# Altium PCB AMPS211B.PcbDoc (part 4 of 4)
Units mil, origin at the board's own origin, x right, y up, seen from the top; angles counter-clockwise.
Board outline 3600 x 2600 mil, 4 copper layers (Top Layer, GND, Power, Bottom Layer), stack 61.6 mil thick; 202 components, 101 nets, 561 pads, 317 vias.
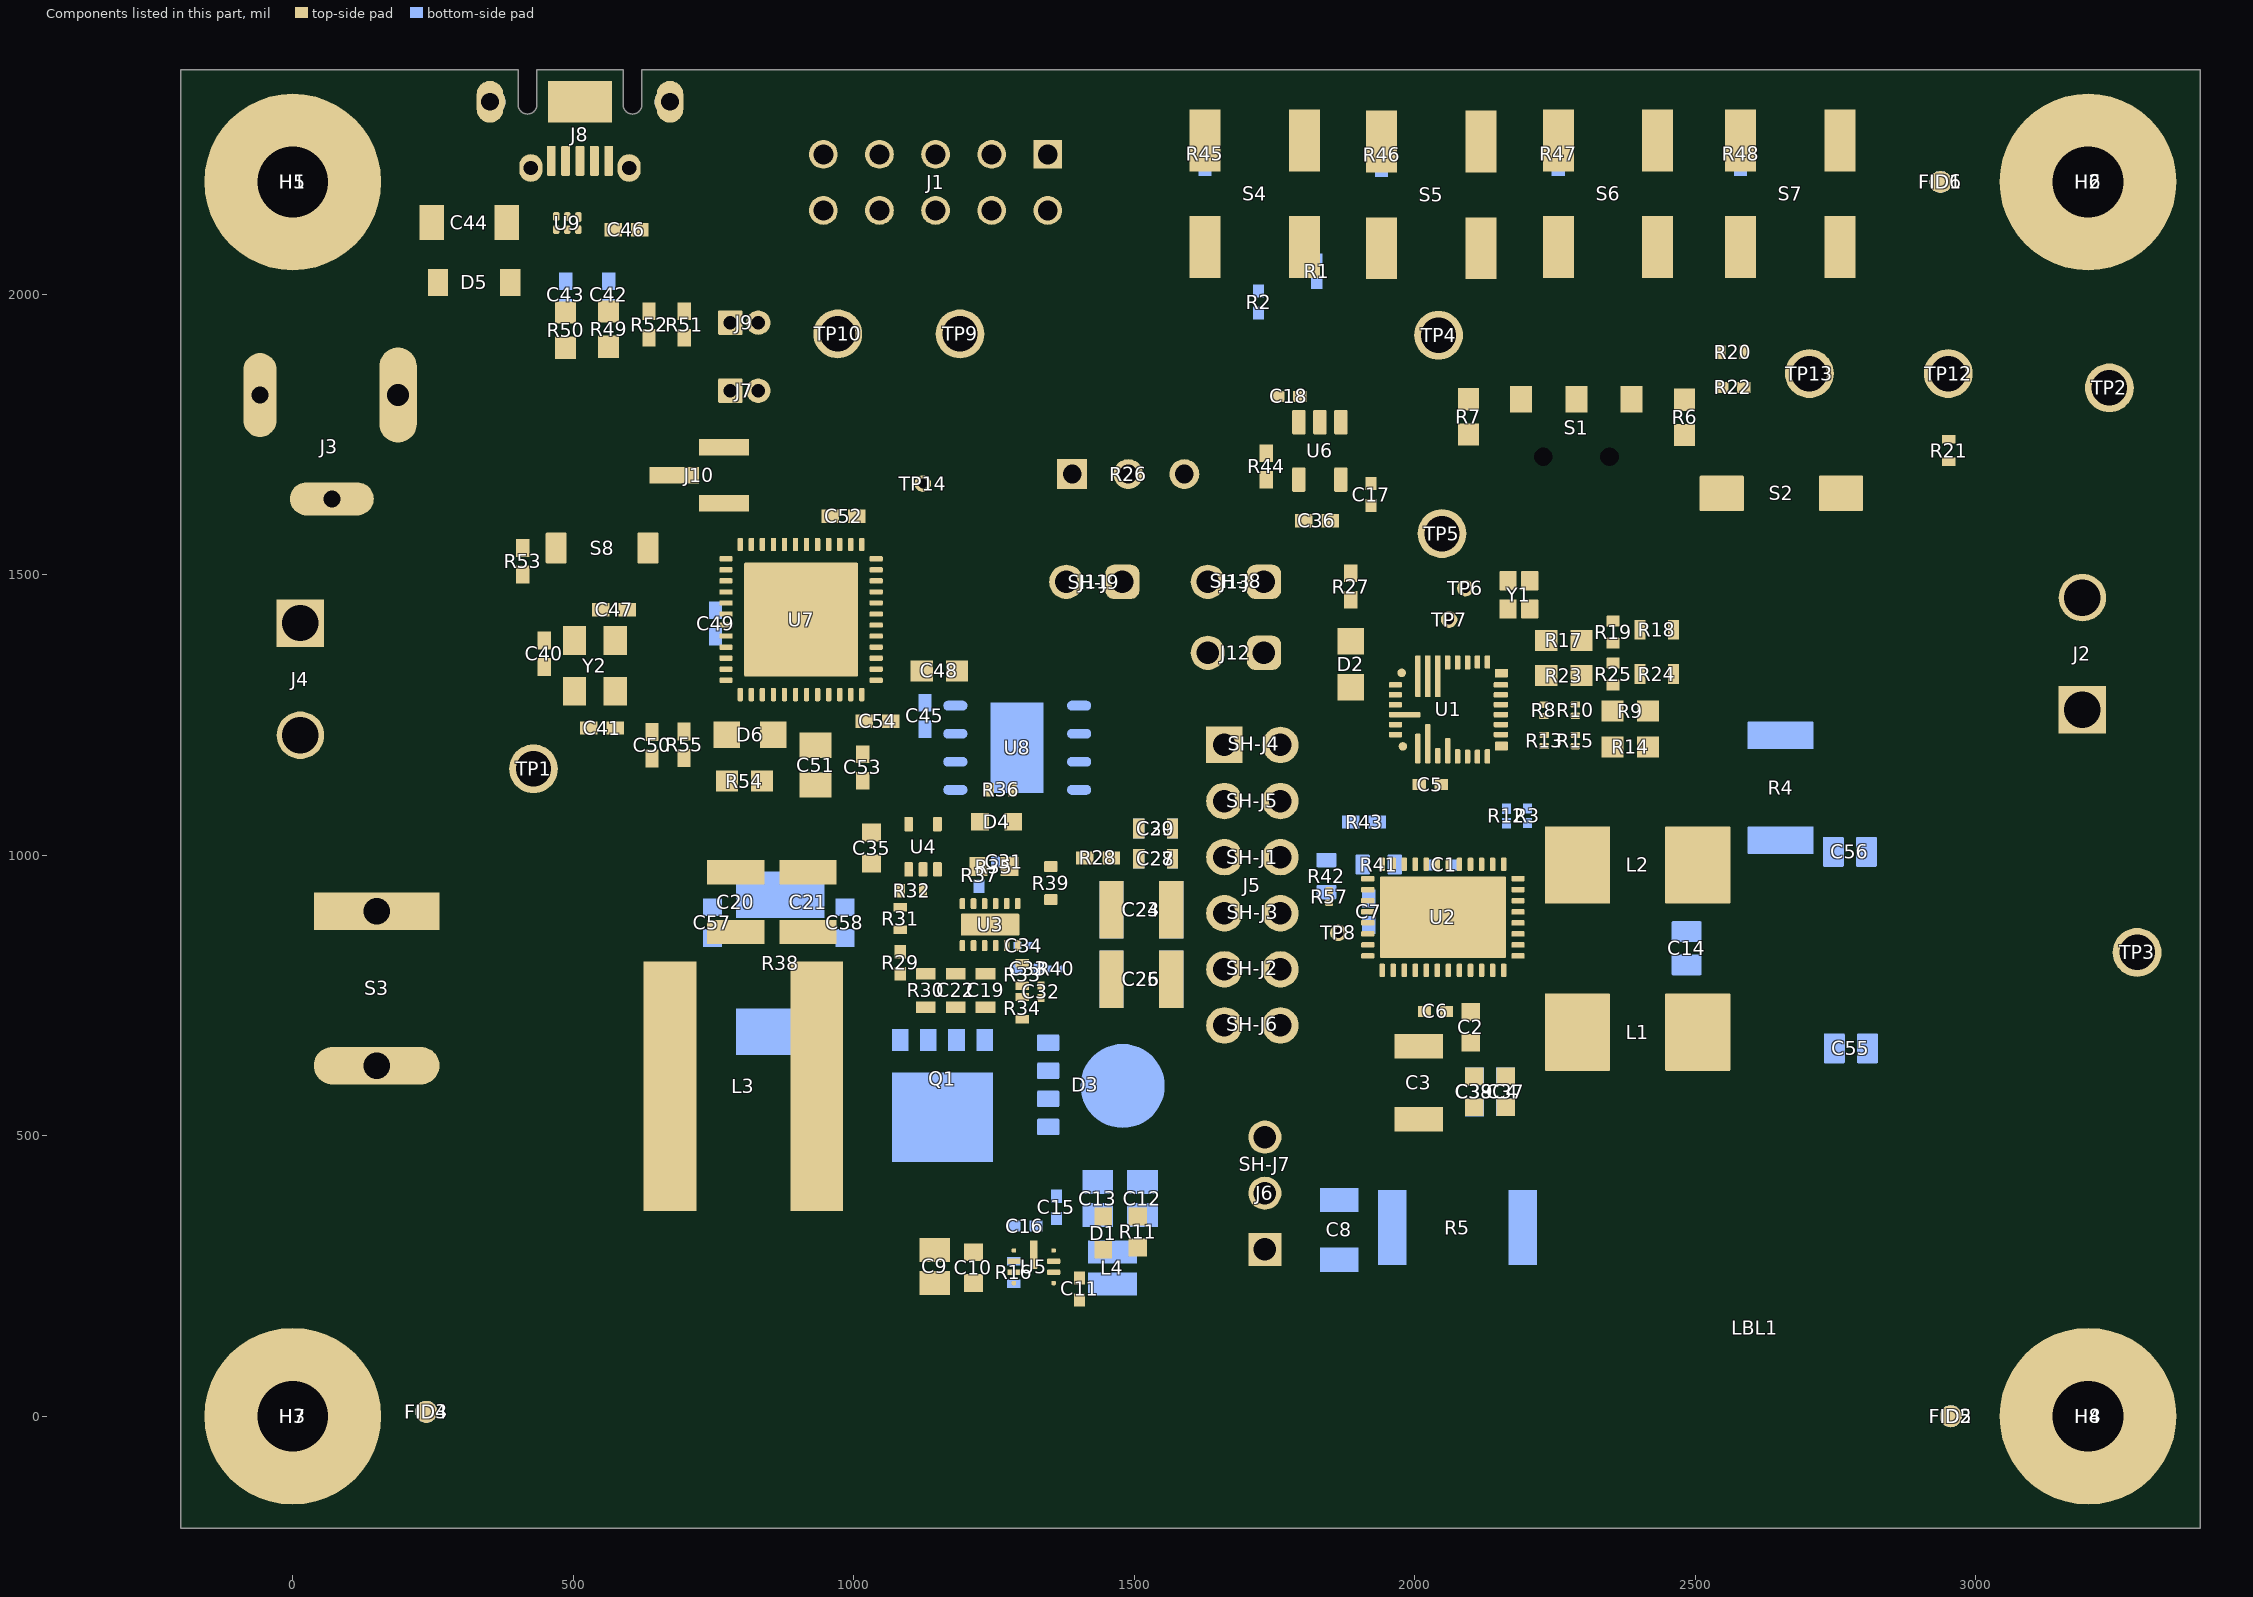
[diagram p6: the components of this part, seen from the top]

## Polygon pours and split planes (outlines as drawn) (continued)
3.3V-DRV on Power "POWER_3.3V-DRV_P401" (solid, remove dead copper, pour order 401): 1709.66,450 1695.84,463.82 1695.84,520.08 1732.77,557 2098,557 2205,664 2205,914 2146,973 2050.62,973 2050.62,1069 2205,1069 2299,975 2299,539 2210,450
VBST on Power "POWER_VBST_P399" (solid, remove dead copper, pour order 399): 1624.65,950.4 1618,957.06 1618,1217.17 1610.49,1224.68 1495.1,1224.68 1481.96,1211.55 1481.96,1089.18 1464.88,1072.1 1219.04,1072.1 1207.82,1060.88 1207.82,992.18 1225.09,974.91 1503.16,974.91 1526.83,951.24 1526.83,659.91 1552.09,634.65 1695.4,634.65 1718.14,657.4 1718.14,922.25 1689.99,950.4
SOURCE on Power "POWER_SOURCE_P400" (solid, remove dead copper, pour order 400): 912.31,805.47 474.72,805.47 425.19,755.95 425.19,562.85 465.43,522.62 519.99,522.62 1320.85,522.62 1334.65,536.42 1334.65,717.52 1246.69,805.47
12VIN_SW on Power "POWER_12VIN_SW_P402" (solid, remove dead copper, pour order 402): 1276.18,469.59 1237.94,507.83 456.64,507.83 276.8,687.68 32.04,687.68 31.65,687.93 -15.06,641.22 -15.06,301.7 214.35,72.3 945.5,72.3 1238.38,72.3 1276.18,110.09
GND on Power "NONET_L-01_P-001" (solid, remove dead copper, pour order 432): 458.32,2100.99 384.46,2027.13 384.46,1291.32 410.88,1269.6 1017.47,1269.6 1032.26,1284.39 1032.26,1484.07 928.16,1588.17 928.16,1808.8 964.57,1845.2 964.57,2037.4 900.98,2100.99
GND on GND "GND_GND_P420" (solid, remove dead copper, pour order 420): 3400,-200 3400,2400 -200,2400 -200,-200
PGND on GND "GND_PGND_P403" (solid, remove dead copper, pour order 403): 1475.4,1794.52 1533.89,1853.02 1878.39,1853.02 1927.18,1804.23 1927.18,1528.38 1724.12,1325.32 1724.12,-98.4 1641.05,-181.47 -188.77,-181.47 -188.79,-181.44 -188.79,1969.1 229.65,1969.1 240.41,1958.3 240.41,1421.35 585.28,1076.47 1435.2,1076.47 1475.4,1116.67

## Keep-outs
Keep-Out Layer:
  lines w5.91: 401.77,2400 401.77,2337.99 ccw(c418.51,2337.74) 435.24,2337.99 435.24,2400 ; 588.78,2400 588.78,2337.99 ccw(c605.51,2337.74) 622.24,2337.99 622.24,2400
  lines w10: -205,-205 3405,-205 3405,2405 -205,2405 -205,-205
  text ".Layer_Name" at 27.84,-1487.26 h60

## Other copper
Top Layer:
  pour cut-out: 2708.66,1441.93 3106.3,1441.93 3106.3,1267.72 2708.66,1267.72
  pour cut-out: 1999.02,1780.51 1978.35,1801.18 1909.45,1801.18 1751.97,1643.7 1702.76,1643.7 1673.23,1673.23 1673.23,1830.71 1692.91,1850.39 1999.02,1850.39
  pour cut-out: 2708.66,1440.94 2708.66,1268.7 2452.76,1268.7 2416.34,1232.28 2416.34,1174.21 2437.01,1153.54 2437.01,1090.55 2429.13,1082.68 2102.36,1082.68 2086.61,1098.43 2086.61,1153.54 2118.11,1185.04 2118.11,1299.21 2259.84,1440.94
  text "1" at 321.27,-4.61 h50
  text ".Layer_Name" at 27.84,-1487.26 h60
Power:
  text "2" at 321.27,-4.61 h50
  text ".Layer_Name" at 27.84,-1487.26 h60
Bottom Layer:
  pour cut-out: 2706.69,1122.05 2706.69,1072.83 2509.84,1072.83 2448.82,1011.81 2440.94,1011.81 2440.94,1106.3 2456.69,1122.05
  pour cut-out: 2708.66,1440.94 2708.66,1122.05 2456.69,1122.05 2437.01,1102.36 2106.3,1102.36 2086.61,1122.05 2086.61,1141.73 2106.3,1161.42 2106.3,1279.53 2267.72,1440.94
  pour cut-out: 2381.89,1417.32 2519.68,1555.12 2519.68,1574.8 2524.89,1580 2574.56,1580 2574.56,1511.57 2480.32,1417.32
  text "4" at 366.72,-10.81 h50
  text ".Layer_Name" at 27.84,-1487.26 h60

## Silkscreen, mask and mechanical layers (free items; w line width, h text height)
Top Overlay:
  circle w6.1: c609.11,1300.84 r3.6
  circle w6.1: c527.76,2137.96 r1.01
  circle w6.1: c247.96,1822.84 r6.29
  circle w6.1: c797.85,1263.45 r2.86
  circle w6.1: c3125.56,856.23 r30
  circle w6.1: c2512.7,1362.53 r30
  circle w6: c2189.48,1861.94 r6
  circle w6: c1571.64,2273.92 r6
  circle w6: c1886.6,2271.95 r6
  circle w6: c2201.56,2273.92 r6
  circle w6: c2526.37,2273.92 r6
  circle w6: c1167.81,842.32 r6
  circle w6: c1062.16,964.12 r6
  circle w6: c1263.88,313.23 r6
  circle w6: c1263.88,313.23 r6
  circle w6: c1062.16,964.12 r6
  circle w6: c1167.81,842.32 r6
  circle w6: c2526.37,2273.92 r6
  circle w6: c2201.56,2273.92 r6
  circle w6: c1886.6,2271.95 r6
  circle w6: c1571.64,2273.92 r6
  circle w6: c2189.48,1861.94 r6
  lines w6: 1141.82,936.56 1148.94,929.44 1148.94,922.54 ; 1307.1,1000.48 1316.5,1009.88 1316.5,1110.55 ; 2106,1503 2166,1563 2307,1563 ; 2316.5,1466.5 2307,1476 2307,1563 ; 2318,1574 2307,1563
  lines w6.1: 706.46,2034.36 734.61,2006.21 ; 887.3,1246.53 898.62,1246.53 ; 1044.1,767.33 1044.1,862.39 1060.13,878.41 ; 1188.56,1107.41 1188.56,1167.99 1212.2,1191.64 ; 1276.94,700.29 1268.64,692 1268.64,560.51 1280.45,548.7 ; 1316.5,1110.55 1324.74,1118.79 ; 1336.95,723.99 1336.95,715.86 1350.72,702.09 ; 1562.71,636.89 1576.62,650.8 1576.62,709.42 ; 1587.89,1090.92 1597.41,1081.39 1597.41,1002.89 1590.36,995.84 ; 2229.07,1176 2239,1176 2263,1152 2347.16,1152 2557,1152 2557,1446 2279.4,1446 2246.62,1413.22 ; 2845.83,406.66 3192.91,406.66 3192.91,908.47 2845.83,908.47 2845.83,406.66
  lines w8: 1515.75,1409.45 1531.5,1409.45 1570.87,1448.82
  text "Custom" at 1607.28,2343.5 h40
  text "Auto" at 1962.6,2343.5 h40
  text "Water" at 2262.8,2343.5 h40
  text "CAL" at 2623.03,2343.5 h40
  text "SCL" at 2120.62,1882.06 h30
  text "SBWTDIO" at 1306.8,1822.3 h30 r90
  text "SBWTCK" at 1096.59,1821.22 h30 r90
  text "SDZ" at 2827.69,1812.43 h30 r90
  text "IRQZ" at 3073.29,1802.63 h30 r90
  text "GND" at 3201,1713 h30
  text "SDA" at 2124,1590 h30
  text "12VIN" at -167.23,1553.24 h30
  text "VarBst" at 1187.1,1553.24 h30
  text "PWMA" at 2421,1523 h30
  text "PWMB" at 2420,1472 h30
  text "RESETZ-MSP" at 1210.72,1383.95 h30
  text "A" at 2528.97,1344.65 h30
  text "RESETZ-ULC" at 1277.65,1309.15 h30
  text "OUTPUT / 0-250Vp / 3.5A / 40-400kHz" at 2608.27,1259.84 h78.74
  text "PGND" at 1485.33,1212.69 h30
  text "GND" at 1825.88,1212.69 h30
  text "Input 9-16V, 8A" at 303.26,1093.73 h98.43 r90
  text "PGND" at 501.04,1070.14 h30
  text "GND" at -170.18,1063.09 h30
  text "A" at 3141.83,838.35 h30
  text "GND" at 3244.19,694.98 h30
  text "VBST" at 1594.58,595.57 h30
  text "PVDD" at 1737.3,595.57 h30
  text "3.3V-DRV" at 1803.24,462.69 h30
  text "3.3V-ULC" at 1803.24,380.02 h30
  text "3.3V-MSP" at 1803.24,287.5 h30
  text "ULC1001-DRV2911EVM" at 2095,287.11 h100
  text "Power Switch" at 555.73,283.86 h120 r90
  text ".Layer_Name" at 27.84,-1487.26 h60
Bottom Overlay:
  lines w6.1: 1175.96,909.31 1206.68,909.31 1215.7,918.34 ; 1234.35,366.03 1234.35,355.99 1247.6,342.74 1264.77,342.74 ; 1235.98,797.23 1272.56,797.23 ; 1354.57,311.17 1354.57,322.32 1361.55,329.3 ; 1364.39,830.99 1364.39,846.98 ; 1453.38,450.01 1457.73,454.36 1586.15,454.36 1590.89,459.1 ; 1553.62,431.4 1637.37,431.4 1650.62,444.65 ; 1574.46,1234.62 1587.31,1221.77 1587.31,1091.13 1612.29,1066.16 1612.29,774.98 1601.4,764.09 ; 1973.94,954.39 1987.96,940.37
  text "'.PRJ_Number'.PCB_Rev" at 2750,0 h100
  text ".Layer_Name" at 27.84,-1487.26 h60
Top Paste:
  region: 382.09,2305.51 346.88,2305.51 338.19,2309.11 331.55,2315.75 327.95,2324.44 327.95,2361.39 331.55,2370.07 338.19,2376.72 346.88,2380.31 382.09,2380.32
  region: 641.93,2305.51 677.14,2305.51 685.82,2309.11 692.47,2315.75 696.06,2324.44 696.06,2361.39 692.47,2370.07 685.82,2376.72 677.14,2380.31 641.93,2380.32
  text ".Layer_Name" at 27.84,-1487.26 h60
Bottom Paste:
  text ".Layer_Name" at 27.84,-1487.26 h60
Top Solder:
  text ".Layer_Name" at 27.84,-1487.26 h60
  text ".Layer_Name" at 27.84,-1487.26 h60
Bottom Solder:
  text ".Layer_Name" at 27.84,-1487.26 h60
Drill Guide:
  text ".Layer_Name" at 27.84,-1487.26 h60
M1 Board Outline:
  the board outline again, w10
  text ".Layer_Name" at 27.84,-1487.26 h60
M2 Board Dimensions:
  rectangle: -549.16,-903.76 -424.16,-778.76
  rectangle: -424.16,-1028.76 -49.16,-903.76
  lines w7: -549.16,-903.76 450.84,-903.76 ; -424.16,-1028.76 -424.16,-778.76 ; -299.16,-1028.76 -299.16,-778.76 ; -49.16,-1028.76 -49.16,-778.76 ; 200.84,-1028.76 200.84,-778.76 ; -549.16,-1028.76 450.84,-1028.76 450.84,-778.76 -549.16,-778.76 -549.16,-1028.76
  lines w10: -200,-200 3400,-200 3400,2400 622.24,2400 622.24,2337.99 cw(c605.51,2337.74) 588.78,2337.99 588.78,2400 435.24,2400 435.24,2337.99 cw(c418.51,2337.74) 401.78,2337.99 401.77,2400 -200,2400 -200,-200
M3 3D STEP Top:
  text ".Layer_Name" at 27.84,-1487.26 h60
M4 3D STEP Bottom:
  text ".Layer_Name" at 27.84,-1487.26 h60
Top M5 Assembly Top/M6 Assembly Bottom:
  lines w6: 7570.15,3565.95 7570.15,4486.58 9154.93,4486.58 ; 7570.15,3638.94 9154.93,3638.94 ; 7570.15,3786.58 9154.93,3786.58 ; 7570.22,3565.58 9154.93,3565.58 ; 7570.22,3713.22 9154.93,3713.22 ; 7570.99,3861.58 9154.61,3861.58 ; 7570.99,3936.58 9154.61,3936.58 ; 7570.99,4011.58 9154.61,4011.58 ; 7570.99,4086.58 9154.61,4086.58 ; 7570.99,4161.58 9154.61,4161.58 ; 7570.99,4236.58 9154.61,4236.58 ; 7570.99,4311.58 9154.61,4311.58 ; 7570.99,4386.58 9154.61,4386.58
  lines w6.1: 7570.15,3786.58 7570.22,3786.51 ; 8052.92,3565.95 8052.92,4486.58 ; 8574.55,3565.95 8574.55,4485.62 ; 9154.93,3565.95 9154.93,4486.58
  lines w10: -841.16,-1558.93 5758.84,-1558.93 ; -841.16,-1355.6 5760.84,-1355.6 ; -841.16,-1152.26 -841.16,-1762.26 3163.84,-1762.26 5760.84,-1762.26 5760.84,-1152.26 -840.66,-1152.26 -840.66,-1762.26 734.84,-1762.26 ; 1623.84,-1762.26 1623.84,-1152.26 ; 2890.84,-1355.6 2890.84,-1152.26 ; 3730.84,-1355.6 3730.84,-1152.26 ; 4352.84,-1768.76 4352.84,-1565.93
  text "Jumper stuff list table" at 7833.34,4548.33 h30
  text "Position" at 8705.13,4422.42 h35
  text "Shunt Ref Des" at 7599.42,4421.7 h35
  text "Header Ref Des" at 8077.59,4419.54 h35
  text "1-2" at 8779.68,4338.41 h35
  text "SH1" at 7739.38,4334.51 h35
  text "J7" at 8272.68,4334.51 h35
  text "J9" at 8272.68,4262.39 h35
  text "1-2" at 8777.7,4262.18 h35
  text "SH2" at 7733.55,4261.08 h35
  text "J5" at 8272.68,4184 h35
  text "5-6" at 8767.98,4183.59 h35
  text "SH-J1" at 7733.55,4181.47 h35
  text "SH-J2" at 7733.55,4112.5 h35
  text "J5" at 8272.68,4112.53 h35
  text "9-10" at 8761.27,4108.38 h35
  text "SH-J3" at 7733.55,4035.13 h35
  text "7-8" at 8770.67,4030.5 h35
  text "J5" at 8272.68,4024.86 h35
  text "SH-J4" at 7733.55,3957.75 h35
  text "1-2" at 8783.86,3955.08 h35
  text "J5" at 8272.68,3953.83 h35
  text "SH-J5" at 7733.55,3882.06 h35
  text "J5" at 8272.68,3880.58 h35
  text "3-4" at 8783.86,3880.08 h35
  text "SH-J6" at 7733.55,3808.05 h35
  text "J5" at 8272.68,3808.44 h35
  text "11-12" at 8783.86,3805.08 h35
  text "1-2" at 8789.86,3735.79 h35
  text "SH-J7" at 7730.9,3734.69 h35
  text "J6" at 8266.16,3729.79 h35
  text "1-2" at 8789.86,3660.99 h35
  text "SH-J8" at 7730.9,3659.89 h35
  text "J13" at 8266.16,3654.99 h35
  text "1-2" at 8789.86,3589.14 h35
  text "SH-J9" at 7730.9,3588.04 h35
  text "J11" at 8266.16,3583.14 h35
  text "COMPONENTS MARKED 'DNP' SHOULD NOT BE POPULATED." at 604.34,-947.26 h60
  text "ASSEMBLY VARIANT:" at 603.84,-1062.76 h60
  text ".VariantName" at 1639.84,-1062.76 h60
  text "PCB VIEWED FROM TOP SIDE" at -777.66,-1284.43 h60
  text "BOARD #:" at 1698.84,-1284.43 h60
  text ".PRJ_Number" at 2244.34,-1284.43 h60
  text "REV:" at 3088.84,-1284.43 h60
  text ".PCB_Rev" at 3380.34,-1284.43 h60
  text "SVN REV:" at 3926.84,-1284.43 h60
  text ".VersionControl_RevNumber" at 4432.84,-1284.43 h60
  text "TID #:" at 1698.84,-1487.76 h60
  text ".TID" at 2244.34,-1487.76 h60
  text "PLOT NAME =" at -777.66,-1693.1 h60
  text ".plot_File_Name" at 27.84,-1693.1 h60
  text "GENERATED    :" at 1700.84,-1693.1 h60
  text ".Print_Date" at 2570.34,-1693.1 h60
  text ".Print_Time" at 3299.34,-1693.1 h60
  text "TEXAS INSTRUMENTS" at 4563.84,-1693.1 h60
Bottom M5 Assembly Top/M6 Assembly Bottom:
  lines w10: -841.66,-1356.1 5760.34,-1356.1 ; -839.66,-1559.43 5760.34,-1559.43 ; 566.34,-1769.26 566.34,-1566.43 ; 1188.34,-1356.1 1188.34,-1152.76 ; 2028.34,-1356.1 2028.34,-1152.76 ; 3295.34,-1762.76 3295.34,-1152.76 ; 4184.34,-1762.76 5759.84,-1762.76 5759.84,-1152.76 -841.66,-1152.76 -841.66,-1762.76 1755.34,-1762.76 5760.34,-1762.76 5760.34,-1152.76
  text "COMPONENTS MARKED 'DNP' SHOULD NOT BE POPULATED." at 5552.84,-946.76 h60
  text ".VariantName" at 4508.84,-1062.76 h60
  text "ASSEMBLY VARIANT:" at 5547.84,-1062.76 h60
  text ".VersionControl_RevNumber" at 486.34,-1284.93 h60
  text "SVN REV:" at 992.34,-1284.93 h60
  text ".PCB_Rev" at 1538.84,-1284.93 h60
  text "REV:" at 1830.34,-1284.93 h60
  text ".PRJ_Number" at 2674.84,-1284.93 h60
  text "BOARD #:" at 3220.34,-1284.93 h60
  text "PCB VIEWED FROM BOTTOM SIDE" at 5696.84,-1284.93 h60
  text ".TID" at 2674.84,-1488.26 h60
  text "TID #:" at 3220.34,-1488.26 h60
  text "TEXAS INSTRUMENTS" at 355.34,-1693.6 h60
  text ".Print_Time" at 1619.84,-1693.6 h60
  text ".Print_Date" at 2348.84,-1693.6 h60
  text "GENERATED    :" at 3218.34,-1693.6 h60
  text ".plot_File_Name" at 4891.34,-1693.6 h60
  text "PLOT NAME =" at 5696.84,-1693.6 h60
M9 Title Sheet:
  drawing of 57 lines, arcs and shapes, not listed
  text "1" at 190.67,7407.74 h70
  text "2" at 2686.34,7407.74 h70
  text "3" at 5175.68,7407.74 h70
  text "4" at 7682.35,7407.74 h70
  text "5" at 10181.34,7407.74 h70
  text "6" at 12686.34,7407.74 h70
  text "A" at -965.66,6264.74 h70
  text "A" at 13834.34,6264.74 h70
  text "B" at -965.66,3884.74 h70
  text "B" at 13834.34,3884.74 h70
  text "C" at -965.66,1509.74 h70
  text "C" at 13834.34,1509.74 h70
  text "PROJECT TITLE:" at 10794.34,-351.26 h45
  text ".PRJ_Title" at 10844.34,-484.59 h70
  text "DESIGNED FOR:" at 10794.34,-652.26 h45
  text ".PRJ_Customer" at 10844.34,-792.26 h70
  text "D" at -965.66,-860.26 h70
  text "D" at 13834.34,-860.26 h70
  text "FILE NAME:" at 10794.34,-952.26 h45
  text ".PCB_File_Name_No_Path" at 10844.34,-1072.26 h70
  text "Texas Instruments (TI) and/or its licensors do not warrant the accuracy or completeness of this specification" at 5824.84,-1234.1 h45
  text "ENGINEER:" at 10794.34,-1242.26 h45
  text "LAYOUT BY:" at 12299.34,-1242.26 h45
  text "or any information contained therein. TI and/or its licensors do not warrant that this design will meet" at 5779.85,-1346.77 h45
  text ".PRJ_Engineer" at 10844.34,-1397.26 h70
  text ".PCB_Layout" at 12349.84,-1397.26 h70
  text "the specifications, will be suitable for your application or fit for any particular purpose, or will operate in" at 5779.85,-1459.43 h45
  text "ALTIUM DESIGNER VERSION:" at 12299.34,-1552.26 h45
  text "an implementation. TI and/or its licensors do not warrant that the design is production worthy. You should" at 5779.85,-1572.1 h45
  text "completely validate and test your design implementation to confirm the system functionality for your application." at 5824.84,-1684.76 h45
  text ".print_Scale" at 10844.34,-1685.59 h70
  text ".Application_BuildNumber" at 12349.84,-1685.59 h70
  text "1" at 190.67,-1892.26 h70
  text "2" at 2686.34,-1892.26 h70
  text "3" at 5175.68,-1892.26 h70
  text "4" at 7682.35,-1892.26 h70
  text "5" at 10181.34,-1892.26 h70
  text "6" at 12299.34,-1897.57 h70
  text "WO:#310005 - 10003-D" at 12495.13,-1897.57 h70
M10 Fab Notes:
  drawing of 199 lines, arcs and shapes, not listed
  text "FAB NOTES:" at -313.49,7134.84 h60
  text "1. BOARD DIMENSION IS : 3600MIL x 2600MIL" at -204.95,6933.26 h60
  text "2. VENDOR MAY ADJUST SOLDERMASK WHEREVER SOLDERMASK PADS ARE THE SAME SIZE (1:1) AS PER THE MANUFACTURING CAPABILITIES AND ALL OTHER SOLDER MASK PADS SHALL NOT BE MODIFIED," at -214.29,6758.42 h60
  text "PROVIDED NO ADJACENT COPPER IS EXPOSED AND NO CONFLICT IS PRODUCED WITH ANY STATED \"VIA TENTING/COVERING\" REQUIREMENTS." at -42.45,6600.66 h60
  text "3. TRACES WITH 6.2MIL TO BE 50 OHMS +/-10% SINGLE ENDED ON EXTERNAL LAYER L1 AND L4(TOP LAYER AND BOTTOM LAYER)." at -194.65,6434.35 h60
  text "4. ALL VIAS ARE TENTED ON TOP SIDES UNLESS OTHERWISE SOLDER MASK IS OPENED IN GERBER." at -201.54,6237.4 h60
  text "DESIGN INFORMATION" at 11832.85,5727.41 h60
  text "MIN. TRACK WIDTH:" at 11188.29,5595.28 h60
  text "6" at 12284.54,5595.29 h60
  text "MIL" at 12439.29,5595.28 h60
  text "5.9" at 12220.59,5481.75 h60
  text "MIN. CLEARANCE:" at 11188.29,5471.16 h60
  text "MIL" at 12439.29,5471.16 h60
  text "19.685" at 12076.02,5348.81 h60
  text "MIN. VIA PAD SIZE:" at 11188.29,5347.03 h60
  text "MIL" at 12439.29,5347.03 h60
  text "0.05mm (2MIL)" at 11883.3,5217.13 h60
  text "MINIMUM ANNULAR RING" at 10859.06,5208.91 h60
  text "EXTERNAL" at 12591.3,5208.91 h60
  text "PER" at 11059.06,5098.78 h60
  text "IPC-D-275 CLASS 2 LEVEL C" at 11279.06,5098.78 h60
  text "MIL, HOLES" at 12767.29,4998.3 h60
  text "+/-" at 12374.84,4989.72 h60
  text "+/-" at 13228.84,4989.72 h60
  text "REGISTRATION TOLERANCES:" at 10859.06,4988.65 h60
  text "METAL" at 12058.84,4988.65 h60
  text "5" at 12635.04,4988.66 h60
  text "3" at 13468.04,4988.66 h60
  text "MIL" at 13584.29,4988.65 h60
  text "HOLE SIZE TOLERANCE (UNLESS OTHERWISE SPECIFIED):" at 10859.06,4890.34 h60
  text "+/-" at 13228.84,4887.47 h60
  text "3" at 13468.04,4886.41 h60
  text "MIL" at 13584.29,4886.4 h60
  text "MATERIAL:" at 10784.3,4748.75 h60
  text "FR-4 High Tg" at 11770.74,4620.23 h60
  text "X" at 11632.22,4617.12 h60
  text "FR-4" at 11205.3,4607.72 h60
  text "OTHER" at 12693.3,4607.72 h60
  text "62 MIL (1.6mm) +/-10%" at 11525.4,4464.69 h60
  text "X" at 11405.3,4462.24 h60
  text "THICKNESS:" at 10859.06,4456.47 h60
  text "OTHER" at 12810.3,4456.47 h60
  text "TOLERANCE:" at 10859.06,4318.16 h60
  text "X" at 11707.3,4318.16 h60
  text "ANSI IPC-6012 TYPE 3 CLASS 2" at 11885.31,4318.16 h60
  text "OTHER +/-" at 11885.3,4173.97 h60
  text "BOW & TWIST:" at 10859.06,4028.78 h60
  text "X" at 11707.3,4028.78 h60
  text "ANSI IPC-6012 TYPE 3 CLASS 2" at 11885.31,4028.78 h60
  text "OTHER +/-" at 11885.3,3882.08 h60
  text "DRILLING:" at 10784.3,3751.46 h60
  text "NC_DRILL FILES" at 12545.29,3646.28 h60
  text "REFERENCE:" at 10859.06,3642.34 h60
  text "X" at 11516.3,3642.24 h60
  text "AS SHOWN" at 11694.29,3642.34 h60
  text "X" at 12417.3,3642.34 h60
  text "OTHER" at 12843.3,3500.09 h60
  text "PTH COPPER THICKNESS:" at 10858.74,3496.56 h60
  text "X" at 11997.98,3496.56 h60
  text "20-30 um" at 12125.97,3496.56 h60
  text "BOARD FINISH:" at 10784.3,3348.96 h60
  text "SILKSCREEN:" at 10939.52,3238.83 h60
  text "X" at 11897.3,3238.83 h60
  text "TOP" at 12014.29,3238.83 h60
  text "X" at 12407.3,3238.83 h60
  text "BOTTOM" at 12525.29,3238.83 h60
  text "SILKSCREEN COLOR:" at 10939.52,3083.65 h60
  text "X" at 11896.3,3083.65 h60
  text "WHITE" at 12014.29,3083.65 h60
  text "OTHER" at 12525.29,3083.65 h60
  text "X" at 12618.25,2941.38 h60
  text "GREEN" at 12145.29,2940.2 h60
  text "OTHER" at 12763.3,2940.2 h60
  text "SOLDER RESIST COLOR:" at 10939.52,2933.33 h60
  text "BLUE" at 13123.7,2928.93 h60
  text "MATTE" at 12145.29,2785.95 h60
  text "X" at 12620.7,2786.51 h60
  text "SEMI-GLOSS" at 12762.84,2785.31 h60
  text "IMMERSION GOLD (ENIG)" at 11845.29,2613.17 h60
  text "ENEPIG" at 13182.84,2605.95 h60
  text "SURFACE FINISH:" at 10784.3,2604.95 h60
  text "X" at 11667.3,2604.95 h60
  text "IMM. TIN/SILVER OR EQUIV" at 11113.84,2467.64 h60
  text "OTHER" at 12545.3,2463.7 h60
  text "ARRAY/PANEL:" at 10784.3,2308.32 h60
  text "CUT AND TRIM PER M1 BOARD OUTLINE" at 11845.3,2300.1 h60
  text "N.C. ROUTE" at 11845.29,2164.13 h60
  text "V. SCORE" at 12711.3,2164.13 h60
  text "CERTIFICATION:" at 10784.3,2035.01 h60
  text "MATERIALS AND WORKMANSHIP FOR ALL PCBS" at 11509.3,2035.01 h60
  text "TO MEET OR EXCEED THE REQUIREMENTS OF:" at 11509.3,1940.94 h60
  text "X" at 11146.8,1812.32 h60
  text "ANSI IPC-A-600F CLASS ->" at 11274.8,1812.32 h60
  text "X" at 12922.8,1812.32 h60
  text "2" at 13032.8,1812.32 h60
  text "1" at 12717.8,1810.82 h60
  text "3" at 13386.8,1810.82 h60
  text "X" at 11958.8,1664.63 h60
  text "RoHS" at 12086.8,1664.63 h60
  text "OTHER" at 12731.2,1664.63 h60
  text "PER ORDER" at 13128.26,1664.63 h60
  text "ALL BOARDS MUST MEET OR EXCEED UL94-V0 REQUIREMENTS." at 10811.84,1510.8 h60
  text "PCB MUST BEAR THE UL94V-0 UL REGISTERED MATERIAL ID NUMBER" at 10811.84,1394.74 h60
  text "ADDITIONAL REQUIREMENTS:" at 10784.3,1225.31 h60
  text "MICROSECTION:" at 10859.06,1118.19 h60
  text "YES" at 11764.8,1118.19 h60
  text "REQUIRED" at 12626.29,973.86 h60
  text "BARE BOARD ELEC. TEST:" at 10859.06,971 h60
  text "NONE" at 12164.8,971 h60
  text "X" at 12508.3,971 h60
  text "PER ORDER" at 13218.3,971 h60
  text "XX MIL VIAS REQUIRE NON-CONDUCTIVE FILL AND PLANARIZE" at 11027.21,766.05 h59
  text "XX MIL VIAS REQUIRE CONDUCTIVE FILL AND PLANARIZE" at 11035.21,662.08 h60
  text "OUTER XX MIL TRACES REQUIRE 50 OHM SINGLE-ENDED IMPEDANCE" at 11034.23,498.69 h58
  text "LAYER 2 & 3 (INNER LAYERS) XX MIL WIDE, XX MIL SPACE / TRACES REQUIRE 100 OHM DIFFERENTIAL IMPEDANCE" at 11026.23,262.98 h60
M11 Gerber Information:
  lines w10: -841.16,-1558.93 5758.84,-1558.93 ; -841.16,-1355.6 5760.84,-1355.6 ; -841.16,-1152.26 -841.16,-1762.26 3163.84,-1762.26 5760.84,-1762.26 5760.84,-1152.26 -840.66,-1152.26 -840.66,-1762.26 734.84,-1762.26 ; 1623.84,-1762.26 1623.84,-1152.26 ; 2890.84,-1355.6 2890.84,-1152.26 ; 3730.84,-1355.6 3730.84,-1152.26 ; 4352.84,-1768.76 4352.84,-1565.93
  text "ALL ARTWORK VIEWED FROM TOP SIDE" at -777.66,-1284.43 h60
  text "BOARD #:" at 1698.84,-1284.43 h60
  text ".PRJ_Number" at 2244.34,-1284.43 h60
  text "REV:" at 3088.84,-1284.43 h60
  text ".PCB_Rev" at 3380.34,-1284.43 h60
  text "SVN REV:" at 3926.84,-1284.43 h60
  text ".VersionControl_RevNumber" at 4432.84,-1284.43 h60
  text "LAYER NAME =" at -777.66,-1487.26 h60
  text "TID #:" at 1698.84,-1487.76 h60
  text ".TID" at 2244.34,-1487.76 h60
  text ".plot_File_Name" at -105.66,-1690.65 h60
  text "PLOT NAME =" at -777.66,-1693.1 h60
  text "GENERATED    :" at 1700.84,-1693.1 h60
  text ".Print_Date" at 2570.34,-1693.1 h60
  text ".Print_Time" at 3299.34,-1693.1 h60
  text "TEXAS INSTRUMENTS" at 4563.84,-1693.1 h60
M12 Stackup:
  drawing of 305 lines, arcs and shapes, not listed
  text "Layer Stackup :" at 4466.4,1937.47 h60
  text "Layer" at 4543.29,1720.63 h60
  text "Name" at 4953.2,1720.63 h60
  text "Material" at 5882.94,1720.63 h60
  text "Thickness" at 6742.71,1720.63 h60
  text "Constant" at 7392.54,1720.63 h60
  text "Board Layer Stack" at 7962.41,1720.63 h60
  text "Top Overlay" at 4953.2,1600.63 h60
  text "Top Solder" at 4953.2,1480.63 h60
  text "Solder Resist" at 5882.94,1480.63 h60
  text "0.40mil" at 6742.71,1480.63 h60
  text "3.5" at 7392.54,1480.63 h60
  text "3" at 4354.11,1365.32 h40
  text "1" at 4543.29,1360.63 h60
  text "Top Layer" at 4953.2,1360.63 h60
  text "Copper" at 5882.94,1360.63 h60
  text "1.40mil" at 6742.71,1360.63 h60
  text "Dielectric 4" at 4953.2,1240.63 h60
  text "PP-006" at 5882.94,1240.63 h60
  text "8.00mil" at 6742.71,1240.63 h60
  text "4.1" at 7392.54,1240.63 h60
  text "2" at 4543.29,1120.63 h60
  text "GND" at 4953.2,1120.63 h60
  text "Copper" at 5882.94,1120.63 h60
  text "1.40mil" at 6742.71,1120.63 h60
  text "Dielectric 2" at 4953.2,1000.63 h60
  text "FR-4 High Tg" at 5882.94,1000.63 h60
  text "40.00mil" at 6742.71,1000.63 h60
  text "4.2" at 7392.54,1000.63 h60
  text "3" at 4543.29,880.63 h60
  text "Power" at 4953.2,880.63 h60
  text "Copper" at 5882.94,880.63 h60
  text "1.40mil" at 6742.71,880.63 h60
  text "Dielectric 3" at 4953.2,760.63 h60
  text "FR-4 High Tg" at 5882.94,760.63 h60
  text "8.00mil" at 6742.71,760.63 h60
  text "4.2" at 7392.54,760.63 h60
  text "3" at 4363.35,646.32 h40
  text "4" at 4543.29,640.63 h60
  text "Bottom Layer" at 4953.2,640.63 h60
  text "Copper" at 5882.94,640.63 h60
  text "1.40mil" at 6742.71,640.63 h60
  text "Bottom Solder" at 4953.2,520.63 h60
  text "Solder Resist" at 5882.94,520.63 h60
  text "0.40mil" at 6742.71,520.63 h60
  text "3.5" at 7392.54,520.63 h60
  text "Bottom Overlay" at 4953.2,400.63 h60
  text "THIS IS AN IMPEDANCE CONTROLLED BOARD" at 5291.96,213.72 h60
  text "NOTE:" at 4396.65,189.43 h60
  text "1.CORE AND PREPREG THICKNESSES ARE UP TO FAB SHOP TO SELECT." at 4397.2,28.89 h60
  text "2.EXTERNAL LAYER CU THICKNESS ARE FINISHED THICKNESS AFTER PLATING." at 4385.16,-145.75 h60
M13 Component Bodies Top:
  text ".Layer_Name" at 27.84,-1487.26 h60
M14 Component Bodies Bottom:
  text ".Layer_Name" at 27.84,-1487.26 h60
M15 Courtyards Top:
  text ".Layer_Name" at 27.84,-1487.26 h60
M16 Courtyards Bottom:
  text ".Layer_Name" at 27.84,-1487.26 h60
Drill Drawing:
  lines w10: -535.95,5329.81 -418.74,5329.81 -418.74,5447 -535.95,5447 -535.95,5329.81 ; -535.95,5502.86 -418.74,5502.86 -418.74,5620.05 -535.95,5620.05 -535.95,5502.86 ; -320.19,3751.9 -253.53,3751.9 -253.53,3818.56 -320.19,3818.56 -320.19,3751.9
  lines w10.1: -386.24,5871.04 303.76,5871.04 ; -386.24,5890.19 303.76,5890.19
  lines w15: -379.98,3106.9 6756.04,3106.9 ; -379.98,5656.9 6756.04,5656.9 ; 170.89,2956.9 170.89,5806.9 ; 770.73,2956.9 770.73,5806.9 ; 1920.4,2956.9 1920.4,5806.9 ; 2426.27,2956.9 2426.27,5806.9 ; 3160.08,2956.9 3160.08,5806.9 ; 4319.74,2956.9 4319.74,5806.9 ; 5677.34,2956.9 5677.34,5806.9 ; -379.98,2956.9 6756.04,2956.9 6756.04,5806.9 -379.98,5806.9 -379.98,2956.9
  text "DRILL CHART:" at -380.68,5923.27 h60
  text "Symbol" at -289.98,5701.9 h72
  text "Count" at 215.89,5701.9 h72
  text "Hole Size" at 815.73,5701.9 h72
  text "Plated" at 1965.4,5701.9 h72
  text "Hole Type" at 2471.27,5701.9 h72
  text "Hole Length" at 3205.08,5701.9 h72
  text "Routed Path Length" at 4364.74,5701.9 h72
  text "Tolerance(Mil)" at 5722.34,5701.9 h72
  text "40" at 215.89,5551.9 h60
  text "7.87mil (0.200mm)" at 815.73,5551.9 h60
  text "PTH" at 1965.4,5551.9 h60
  text "Round" at 2471.27,5551.9 h60
  text "-" at 3205.08,5551.9 h60
  text "-" at 4364.74,5551.9 h60
  text "+0/-7.87" at 5722.34,5551.9 h60
  text "A" at -319.07,5541.91 h66.67
  text "4" at -512.59,5509.47 h70
  text "277" at 215.89,5401.9 h60
  text "10.00mil (0.254mm)" at 815.73,5401.9 h60
  text "PTH" at 1965.4,5401.9 h60
  text "Round" at 2471.27,5401.9 h60
  text "-" at 3205.08,5401.9 h60
  text "-" at 4364.74,5401.9 h60
  text "+0/-10" at 5722.34,5401.9 h60
  text "B" at -319.07,5391.91 h66.67
  text "4" at -513.89,5345.77 h70
  text "4" at 215.89,5251.9 h60
  text "17.72mil (0.450mm)" at 815.73,5251.9 h60
  text "PTH" at 1965.4,5251.9 h60
  text "Round" at 2471.27,5251.9 h60
  text "-" at 3205.08,5251.9 h60
  text "-" at 4364.74,5251.9 h60
  text "+/-3" at 5722.34,5251.9 h60
  text "C" at -319.07,5241.91 h66.67
  text "4" at 215.89,5101.9 h60
  text "23.62mil (0.600mm)" at 815.73,5101.9 h60
  text "PTH" at 1965.4,5101.9 h60
  text "Round" at 2471.27,5101.9 h60
  text "-" at 3205.08,5101.9 h60
  text "-" at 4364.74,5101.9 h60
  text "+/-3" at 5722.34,5101.9 h60
  text "D" at -319.07,5091.91 h66.67
  text "2" at 215.89,4951.9 h60
  text "25.59mil (0.650mm)" at 815.73,4951.9 h60
  text "PTH" at 1965.4,4951.9 h60
  text "Slot" at 2471.27,4951.9 h60
  text "33.47mil (0.850mm)" at 3205.08,4951.9 h60
  text "7.87mil (0.200mm)" at 4364.74,4951.9 h60
  text "+/-3" at 5722.34,4951.9 h60
  text "E" at -319.07,4941.91 h66.67
  text "2" at 215.89,4801.9 h60
  text "29.92mil (0.760mm)" at 815.73,4801.9 h60
  text "PTH" at 1965.4,4801.9 h60
  text "Slot" at 2471.27,4801.9 h60
  text "120.08mil (3.050mm)" at 3205.08,4801.9 h60
  text "90.16mil (2.290mm)" at 4364.74,4801.9 h60
  text "+/-3" at 5722.34,4801.9 h60
  text "F" at -319.07,4791.91 h66.67
  text "2" at 215.89,4651.9 h60
  text "31.50mil (0.800mm)" at 815.73,4651.9 h60
  text "PTH" at 1965.4,4651.9 h60
  text "Slot" at 2471.27,4651.9 h60
  text "59.06mil (1.500mm)" at 3205.08,4651.9 h60
  text "27.56mil (0.700mm)" at 4364.74,4651.9 h60
  text "+/-3" at 5722.34,4651.9 h60
  text "G" at -319.07,4641.91 h66.67
  text "2" at 215.89,4501.9 h60
  text "33.47mil (0.850mm)" at 815.73,4501.9 h60
  text "NPTH" at 1965.4,4501.9 h60
  text "Round" at 2471.27,4501.9 h60
  text "-" at 3205.08,4501.9 h60
  text "-" at 4364.74,4501.9 h60
  text "+/-2" at 5722.34,4501.9 h60
  text "I" at -307.97,4491.91 h66.67
  text "3" at 215.89,4351.9 h60
  text "33.47mil (0.850mm)" at 815.73,4351.9 h60
  text "PTH" at 1965.4,4351.9 h60
  text "Round" at 2471.27,4351.9 h60
  text "-" at 3205.08,4351.9 h60
  text "-" at 4364.74,4351.9 h60
  text "+/-3" at 5722.34,4351.9 h60
  text "H" at -319.07,4341.91 h66.67
  text "10" at 215.89,4201.9 h60
  text "35.43mil (0.900mm)" at 815.73,4201.9 h60
  text "PTH" at 1965.4,4201.9 h60
  text "Round" at 2471.27,4201.9 h60
  text "-" at 3205.08,4201.9 h60
  text "-" at 4364.74,4201.9 h60
  text "+/-3" at 5722.34,4201.9 h60
  text "K" at -319.07,4191.91 h66.67
  text "1" at 215.89,4051.9 h60
  text "39.76mil (1.010mm)" at 815.73,4051.9 h60
  text "PTH" at 1965.4,4051.9 h60
  text "Slot" at 2471.27,4051.9 h60
  text "140.16mil (3.560mm)" at 3205.08,4051.9 h60
  text "100.39mil (2.550mm)" at 4364.74,4051.9 h60
  text "+/-3" at 5722.34,4051.9 h60
  text "L" at -319.07,4041.91 h66.67
  text "15" at 215.89,3901.9 h60
  text "40.00mil (1.016mm)" at 815.73,3901.9 h60
  text "PTH" at 1965.4,3901.9 h60
  text "Round" at 2471.27,3901.9 h60
  text "-" at 3205.08,3901.9 h60
  text "-" at 4364.74,3901.9 h60
  text "+/-3" at 5722.34,3901.9 h60
  text "M" at -319.07,3891.91 h66.67
  text "6" at 215.89,3751.9 h60
  text "40.16mil (1.020mm)" at 815.73,3751.9 h60
  text "PTH" at 1965.4,3751.9 h60
  text "Round" at 2471.27,3751.9 h60
  text "-" at 3205.08,3751.9 h60
  text "-" at 4364.74,3751.9 h60
  text "2" at 215.89,3601.9 h60
  text "47.24mil (1.200mm)" at 815.73,3601.9 h60
  text "PTH" at 1965.4,3601.9 h60
  text "Slot" at 2471.27,3601.9 h60
  text "204.72mil (5.200mm)" at 3205.08,3601.9 h60
  text "157.48mil (4.000mm)" at 4364.74,3601.9 h60
  text "+/-3" at 5722.34,3601.9 h60
  text "N" at -319.07,3591.91 h66.67
  text "9" at 215.89,3451.9 h60
  text "63.00mil (1.600mm)" at 815.73,3451.9 h60
  text "PTH" at 1965.4,3451.9 h60
  text "Round" at 2471.27,3451.9 h60
  text "-" at 3205.08,3451.9 h60
  text "-" at 4364.74,3451.9 h60
  text "+/-3" at 5722.34,3451.9 h60
  text "P" at -319.07,3441.91 h66.67
  text "4" at 215.89,3301.9 h60
  text "64.96mil (1.650mm)" at 815.73,3301.9 h60
  text "PTH" at 1965.4,3301.9 h60
  text "Round" at 2471.27,3301.9 h60
  text "-" at 3205.08,3301.9 h60
  text "-" at 4364.74,3301.9 h60
  text "+/-3" at 5722.34,3301.9 h60
  text "Q" at -319.07,3291.91 h66.67
  text "4" at 215.89,3151.9 h60
  text "125.98mil (3.200mm)" at 815.73,3151.9 h60
  text "PTH" at 1965.4,3151.9 h60
  text "Round" at 2471.27,3151.9 h60
  text "-" at 3205.08,3151.9 h60
  text "-" at 4364.74,3151.9 h60
  text "+/-3" at 5722.34,3151.9 h60
  text "R" at -319.07,3141.91 h66.67
  text "387 Total" at 215.89,3001.9 h60
  text "Slot definitions :" at -289.98,2856.92 h60
  text "Routed Path Length" at 742.71,2856.92 h60
  text "= Calculated from tool start centre position to tool end centre position." at 1845.37,2856.92 h60
  text "Hole Length" at 742.71,2756.95 h60
  text "= Routed Path Length + Tool Size = Slot length as defined in the PCB layout" at 1435.51,2756.95 h60
  text "FAB" at 27.84,-1487.26 h60
M17 Embedded Cavity:
  text ".Layer_Name" at 27.84,-1487.26 h60
M18 Embedded Assembly:
  text ".Layer_Name" at 27.84,-1487.26 h60
M19 Embedded Keepout:
  text ".Layer_Name" at 27.84,-1487.26 h60

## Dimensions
605.51,2337.74 to 1104.31,2337.74 on M2 Board Dimensions
588.78,2400 to 622.24,2400 on M2 Board Dimensions
435.24,2400 to 588.78,2400 on M2 Board Dimensions
401.77,2400 to 435.24,2400 on M2 Board Dimensions
0,0 to 72.31,-255.76 on M2 Board Dimensions
0,0 to 3400,-200 on M2 Board Dimensions
0,0 to -200,-200 on M2 Board Dimensions
0,0 to -200,2400 on M2 Board Dimensions
0,0 to -200,-200 on M2 Board Dimensions
-549.16,-1028.76 to 450.84,-1028.76 on M2 Board Dimensions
